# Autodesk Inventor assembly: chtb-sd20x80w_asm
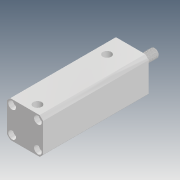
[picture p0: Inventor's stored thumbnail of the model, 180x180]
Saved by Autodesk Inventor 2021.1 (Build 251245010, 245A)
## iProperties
Company: Microsoft
Created: 2018-05
Part Number: chtb-sd20x80w_asm
Description: STEP AP214
Document SubType Name: Assembly
Designer: user
Title: chtb-sd20x80w_asm.STEP
Author: Windows
Revision Number: ÈÎºÎ
Sending System: SolidWorks 2015
Preprocessor: SwSTEP 2.0
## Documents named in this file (4)
- D:\Vault_2016\Projekty\Clamptek\Hydraulic\CHTB\CHTB-20\Inventor\CHTB-SD20x80W\chtb-sd20x80w_asm.iam
- D:\Vault_2016\Projekty\Clamptek\Hydraulic\CHTB\CHTB-20\Inventor\CHTB-SD20x80W\CHTB-SD20X80NBT.ipt
- D:\Vault_2016\Projekty\Clamptek\Hydraulic\CHTB\CHTB-20\Inventor\CHTB-SD20x80W\CHTB-SD20X80WHSG.ipt
- D:\Vault_2016\Projekty\Clamptek\Hydraulic\CHTB\CHTB-20\Inventor\CHTB-SD20x80W\QG.ipt
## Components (3 placed, 3 different names)
1. CHTB-SD20X80NBT_1
2. CHTB-SD20X80WHSG_2
3. QG_3
